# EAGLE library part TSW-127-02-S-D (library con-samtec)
THROUGH-HOLE .025" SQ POST HEADER Source: Samtec TSW.pdf
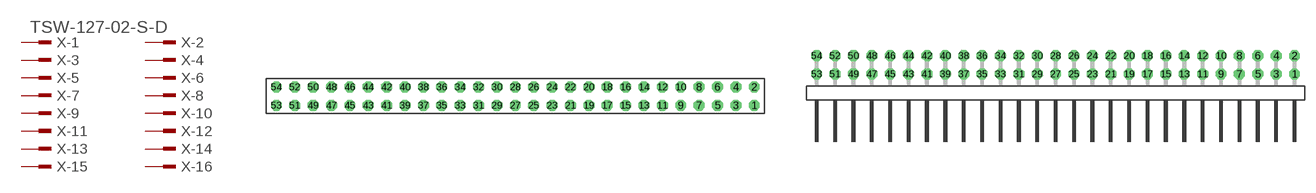
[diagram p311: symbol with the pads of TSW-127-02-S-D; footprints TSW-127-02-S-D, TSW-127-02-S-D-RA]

Designator prefix X; gates -1=MPINV -2=MPIN -3=MPIN -4=MPIN -5=MPIN -6=MPIN -7=MPIN -8=MPIN -9=MPIN -10=MPIN -11=MPIN -12=MPIN -13=MPIN -14=MPIN -15=MPIN -16=MPIN -17=MPIN -18=MPIN -19=MPIN -20=MPIN -21=MPIN -22=MPIN -23=MPIN -24=MPIN -25=MPIN -26=MPIN -27=MPIN -28=MPIN -29=MPIN -30=MPIN -31=MPIN -32=MPIN -33=MPIN -34=MPIN -35=MPIN -36=MPIN -37=MPIN -38=MPIN -39=MPIN -40=MPIN -41=MPIN -42=MPIN -43=MPIN -44=MPIN -45=MPIN -46=MPIN -47=MPIN -48=MPIN -49=MPIN -50=MPIN -51=MPIN -52=MPIN -53=MPIN -54=MPIN

## TSW-127-02-S-D (OC_FARNELL: unknown; OC_NEWARK: unknown)  [TSW-127-02-S-D]
1  -1:1  pas
2  -2:1  pas
3  -3:1  pas
4  -4:1  pas
5  -5:1  pas
6  -6:1  pas
7  -7:1  pas
8  -8:1  pas
9  -9:1  pas
10  -10:1  pas
11  -11:1  pas
12  -12:1  pas
13  -13:1  pas
14  -14:1  pas
15  -15:1  pas
16  -16:1  pas
17  -17:1  pas
18  -18:1  pas
19  -19:1  pas
20  -20:1  pas
21  -21:1  pas
22  -22:1  pas
23  -23:1  pas
24  -24:1  pas
25  -25:1  pas
26  -26:1  pas
27  -27:1  pas
28  -28:1  pas
29  -29:1  pas
30  -30:1  pas
31  -31:1  pas
32  -32:1  pas
33  -33:1  pas
34  -34:1  pas
35  -35:1  pas
36  -36:1  pas
37  -37:1  pas
38  -38:1  pas
39  -39:1  pas
40  -40:1  pas
41  -41:1  pas
42  -42:1  pas
43  -43:1  pas
44  -44:1  pas
45  -45:1  pas
46  -46:1  pas
47  -47:1  pas
48  -48:1  pas
49  -49:1  pas
50  -50:1  pas
51  -51:1  pas
52  -52:1  pas
53  -53:1  pas
54  -54:1  pas

## TSW-127-02-S-D-RA (OC_FARNELL: unknown; OC_NEWARK: unknown)  [TSW-127-02-S-D-RA]
Pads as for TSW-127-02-S-D

## Footprint TSW-127-02-S-D (pad centres in mm)
THROUGH-HOLE .025" SQ POST HEADER Source: Samtec TSW.pdf
drill 1 pad 1.5 octagon: 1 33.02,-1.27; 2 33.02,1.27; 3 30.48,-1.27; 4 30.48,1.27; 5 27.94,-1.27; 6 27.94,1.27; 7 25.4,-1.27; 8 25.4,1.27; 9 22.86,-1.27; 10 22.86,1.27; 11 20.32,-1.27; 12 20.32,1.27; 13 17.78,-1.27; 14 17.78,1.27; 15 15.24,-1.27; 16 15.24,1.27; 17 12.7,-1.27; 18 12.7,1.27; 19 10.16,-1.27; 20 10.16,1.27; 21 7.62,-1.27; 22 7.62,1.27; 23 5.08,-1.27; 24 5.08,1.27; 25 2.54,-1.27; 26 2.54,1.27; 27 0,-1.27; 28 0,1.27; 29 -2.54,-1.27; 30 -2.54,1.27; 31 -5.08,-1.27; 32 -5.08,1.27; 33 -7.62,-1.27; 34 -7.62,1.27; 35 -10.16,-1.27; 36 -10.16,1.27; 37 -12.7,-1.27; 38 -12.7,1.27; 39 -15.24,-1.27; 40 -15.24,1.27; 41 -17.78,-1.27; 42 -17.78,1.27; 43 -20.32,-1.27; 44 -20.32,1.27; 45 -22.86,-1.27; 46 -22.86,1.27; 47 -25.4,-1.27; 48 -25.4,1.27; 49 -27.94,-1.27; 50 -27.94,1.27; 51 -30.48,-1.27; 52 -30.48,1.27; 53 -33.02,-1.27; 54 -33.02,1.27

## Footprint TSW-127-02-S-D-RA (pad centres in mm)
THROUGH-HOLE .025" SQ POST HEADER Source: Samtec TSW.pdf
drill 1 pad 1.5 octagon: 1 33.02,1.524; 2 33.02,4.064; 3 30.48,1.524; 4 30.48,4.064; 5 27.94,1.524; 6 27.94,4.064; 7 25.4,1.524; 8 25.4,4.064; 9 22.86,1.524; 10 22.86,4.064; 11 20.32,1.524; 12 20.32,4.064; 13 17.78,1.524; 14 17.78,4.064; 15 15.24,1.524; 16 15.24,4.064; 17 12.7,1.524; 18 12.7,4.064; 19 10.16,1.524; 20 10.16,4.064; 21 7.62,1.524; 22 7.62,4.064; 23 5.08,1.524; 24 5.08,4.064; 25 2.54,1.524; 26 2.54,4.064; 27 0,1.524; 28 0,4.064; 29 -2.54,1.524; 30 -2.54,4.064; 31 -5.08,1.524; 32 -5.08,4.064; 33 -7.62,1.524; 34 -7.62,4.064; 35 -10.16,1.524; 36 -10.16,4.064; 37 -12.7,1.524; 38 -12.7,4.064; 39 -15.24,1.524; 40 -15.24,4.064; 41 -17.78,1.524; 42 -17.78,4.064; 43 -20.32,1.524; 44 -20.32,4.064; 45 -22.86,1.524; 46 -22.86,4.064; 47 -25.4,1.524; 48 -25.4,4.064; 49 -27.94,1.524; 50 -27.94,4.064; 51 -30.48,1.524; 52 -30.48,4.064; 53 -33.02,1.524; 54 -33.02,4.064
